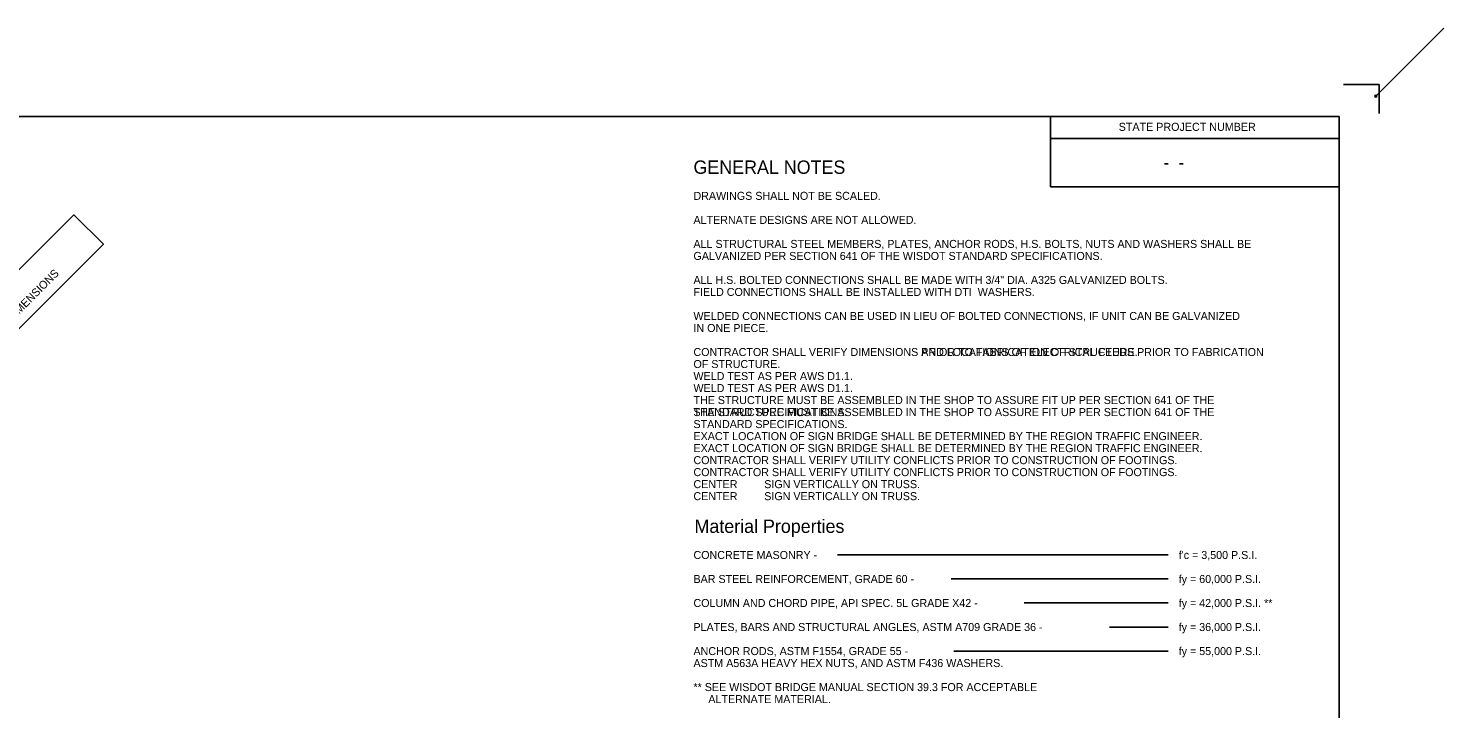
# Model space of a CAD drawing. Extents: x -21 to 58.5, y -16 to 40.8.
# Drawn here: x 8.74 to 58.48, y 15.43 to 39.32 of the extents above; entities that cross this region are included whole.
import ezdxf

# ---------------------------------------------------------------- set-up
doc = ezdxf.new("R2010")
doc.units = 0
for name, color, linetype in [('Level 1', 7, 'Continuous'), ('Level 10', 7, 'Continuous'), ('Level 11', 7, 'Continuous'), ('Level 2', 7, 'Continuous'), ('Level 49', 7, 'Continuous')]:
    doc.layers.add(name, color=color, linetype=linetype)

msp = doc.modelspace()

# ---------------------------------------------------------------- linework, layer by layer
at = {"layer": 'Level 1'}
for p, q in [((56.21, 37.351), (54.963, 37.351)), ((56.21, 36.327), (56.21, 37.351)), ((54.804, 36.226), (-15.791, 36.226)), ((44.665, 36.226), (44.665, 33.761)), ((54.804, -11.023), (54.804, 36.226)), ((44.665, 35.451), (54.804, 35.451)), ((44.665, 33.761), (54.804, 33.761))]:
    msp.add_line(p, q, dxfattribs=at)
at = {"layer": 'Level 11'}
msp.add_lwpolyline([(1.993, 24.418), (10.347, 32.772), (11.379, 31.74), (3.025, 23.386)], close=True, dxfattribs=at)
at = {"layer": 'Level 2'}
for p, q in [((56.095, 36.936), (58.482, 39.323)), ((37.177, 20.827), (48.804, 20.827)), ((41.176, 19.983), (48.804, 19.983)), ((43.74, 19.14), (48.804, 19.14)), ((46.738, 18.296), (48.804, 18.296)), ((41.264, 17.452), (48.804, 17.452))]:
    msp.add_line(p, q, dxfattribs=at)
at = {"layer": 'Level 49'}
msp.add_circle((56.095, 36.936), 0.0342, dxfattribs=at)

# ---------------------------------------------------------------- texts
at = {"layer": 'Level 1'}
for s, height, p in [('STATE PROJECT NUMBER', 0.28181, (47.061, 35.722)), ('GENERAL NOTES', 0.46945, (32.117, 34.212)), ('    -  -  ', 0.443, (47.979, 34.391)), ('Material Properties', 0.46945, (32.153, 21.6))]:
    msp.add_text(s, height=height, dxfattribs=at).set_placement(p)
at = {"layer": 'Level 10'}
for s, p in [('DRAWINGS SHALL NOT BE SCALED.', (32.117, 33.298)), ('ALTERNATE DESIGNS ARE NOT ALLOWED.', (32.117, 32.454)), ('ALL STRUCTURAL STEEL MEMBERS, PLATES, ANCHOR RODS, H.S. BOLTS, NUTS AND WASHERS SHALL BE', (32.117, 31.61)), ('GALVANIZED PER SECTION 641 OF THE WISDOT STANDARD SPECIFICATIONS.', (32.117, 31.188)), ('ALL H.S. BOLTED CONNECTIONS SHALL BE MADE WITH 3/4" DIA. A325 GALVANIZED BOLTS.', (32.117, 30.345)), ('FIELD CONNECTIONS SHALL BE INSTALLED WITH DTI  WASHERS.', (32.117, 29.923)), ('WELDED CONNECTIONS CAN BE USED IN LIEU OF BOLTED CONNECTIONS, IF UNIT CAN BE GALVANIZED', (32.117, 29.079)), ('IN ONE PIECE.', (32.117, 28.657)), ('CONTRACTOR SHALL VERIFY DIMENSIONS PRIOR TO FABRICATION OF STRUCTURE.', (32.117, 27.813)), ('WELD TEST AS PER AWS D1.1.', (32.117, 26.97)), ('THE STRUCTURE MUST BE ASSEMBLED IN THE SHOP TO ASSURE FIT UP PER SECTION 641 OF THE ', (32.117, 26.126)), ('STANDARD SPECIFICATIONS.', (32.117, 25.704)), ('EXACT LOCATION OF SIGN BRIDGE SHALL BE DETERMINED BY THE REGION TRAFFIC ENGINEER.', (32.117, 24.86)), ('CONTRACTOR SHALL VERIFY UTILITY CONFLICTS PRIOR TO CONSTRUCTION OF FOOTINGS.', (32.117, 24.016)), ('CENTER         SIGN VERTICALLY ON TRUSS.', (32.117, 23.173))]:
    msp.add_text(s, height=0.28125, dxfattribs=at).set_placement(p)
at = {"layer": 'Level 11'}
for s, p in [('DRAWINGS SHALL NOT BE SCALED.', (32.117, 33.298)), ('ALTERNATE DESIGNS ARE NOT ALLOWED.', (32.117, 32.454)), ('ALL STRUCTURAL STEEL MEMBERS, PLATES, ANCHOR RODS, H.S. BOLTS, NUTS AND WASHERS SHALL BE', (32.117, 31.61)), ('GALVANIZED PER SECTION 641 OF THE WISDOT STANDARD SPECIFICATIONS.', (32.117, 31.188)), ('ALL H.S. BOLTED CONNECTIONS SHALL BE MADE WITH 3/4" DIA. A325 GALVANIZED BOLTS.', (32.117, 30.345)), ('FIELD CONNECTIONS SHALL BE INSTALLED WITH DTI  WASHERS.', (32.117, 29.923)), ('WELDED CONNECTIONS CAN BE USED IN LIEU OF BOLTED CONNECTIONS, IF UNIT CAN BE GALVANIZED', (32.117, 29.079)), ('IN ONE PIECE.', (32.117, 28.657)), ('CONTRACTOR SHALL VERIFY DIMENSIONS AND LOCATIONS OF ELECTRICAL FEEDS PRIOR TO FABRICATION', (32.117, 27.813)), ('OF STRUCTURE.', (32.117, 27.391)), ('WELD TEST AS PER AWS D1.1.', (32.117, 26.548)), ('THE STRUCTURE MUST BE ASSEMBLED IN THE SHOP TO ASSURE FIT UP PER SECTION 641 OF THE', (32.117, 25.704)), ('STANDARD SPECIFICATIONS.', (32.117, 25.282)), ('EXACT LOCATION OF SIGN BRIDGE SHALL BE DETERMINED BY THE REGION TRAFFIC ENGINEER.', (32.117, 24.438)), ('CONTRACTOR SHALL VERIFY UTILITY CONFLICTS PRIOR TO CONSTRUCTION OF FOOTINGS.', (32.117, 23.595)), ('CENTER         SIGN VERTICALLY ON TRUSS.', (32.117, 22.751))]:
    msp.add_text(s, height=0.28125, dxfattribs=at).set_placement(p)
msp.add_text('SUPPORT BRACKETS LAYOUT AND DIMENSIONS', height=0.28125, rotation=45, dxfattribs=at).set_placement((3.518, 24.367))
at = {"layer": 'Level 2'}
for s, p in [('CONCRETE MASONRY -', (32.117, 20.685)), ("f'c = 3,500 P.S.I.", (49.169, 20.685)), ('BAR STEEL REINFORCEMENT, GRADE 60 -', (32.117, 19.842)), ('fy = 60,000 P.S.I.', (49.169, 19.842)), ('COLUMN AND CHORD PIPE, API SPEC. 5L GRADE X42 -', (32.117, 18.998)), ('fy = 42,000 P.S.I. **', (49.169, 18.998)), ('PLATES, BARS AND STRUCTURAL ANGLES, ASTM A709 GRADE 36 -', (32.117, 18.154)), ('fy = 36,000 P.S.I.', (49.169, 18.154)), ('ANCHOR RODS, ASTM F1554, GRADE 55 -', (32.117, 17.31)), ('fy = 55,000 P.S.I.', (49.169, 17.31)), ('ASTM A563A HEAVY HEX NUTS, AND ASTM F436 WASHERS.', (32.117, 16.889)), ('** SEE WISDOT BRIDGE MANUAL SECTION 39.3 FOR ACCEPTABLE ', (32.117, 16.045)), ('     ALTERNATE MATERIAL.', (32.117, 15.623))]:
    msp.add_text(s, height=0.28125, dxfattribs=at).set_placement(p)

doc.saveas('drawing.dxf')
